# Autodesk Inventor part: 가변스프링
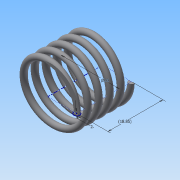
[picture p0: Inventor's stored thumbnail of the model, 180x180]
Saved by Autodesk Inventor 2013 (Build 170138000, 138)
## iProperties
Created: 2019-01
Part Number: 가변스프링
Material: 일반
Document SubType Name: Modeling
Designer: Administrator
Density: 1 g/cm^3
Mass: 0.971845 g
Surface Area: 19.6285 cm^2
Volume: 0.971845 cm^3
Author: Administrator
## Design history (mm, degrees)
sketch "스케치1"
  geometry: L1 (0, 0)-(10, 0); L2 (10, 0)-(10, 18.85); L3 (10, 18.85)-(0, 18.85); L4 (0, 18.85)-(0, 0); C1 r 1 at (10, 0)
  constraints: 8 end point, 2 parallel, 1 centre point, 1 coincident, 1 horizontal, 1 perpendicular
  dimensions: "d0" = 2 diameter of C1; "d1" = 20 diameter of L2 L4; "d2" = 18.85 distance between parallel lines of L1 L3 (derived)
feature "코일1" pitch "d3" = 10; turns "d5" = 5; dims "d4" = 18.85 (= d2), "d6" = 0, angle "d7" = 90 deg, angle "d8" = 90 deg, "d9" = 0, "d10" = 0
sketch "스케치2"
  geometry: L1 (-9, 0)-(-11, 0) reference; L2 (-9, 0)-(-11, 0) reference; 1 further point
  constraints: 2 horizontal alignment
extrude "돌출1" cut sketch "스케치2" stored distance "d11" = 10; taper "d12" = 0 deg
node "작업 평면1"
sketch "스케치3"
  geometry: L1 (9, 0)-(11, 0) reference; 1 further point
  constraints: 1 horizontal alignment
extrude "돌출2" cut sketch "스케치3" stored distance "d13" = 10; taper "d14" = 0 deg
node "솔리드1"
node "절단 모서리 투영1"
node "절단 모서리 투영2"
node "절단 모서리 투영3"
